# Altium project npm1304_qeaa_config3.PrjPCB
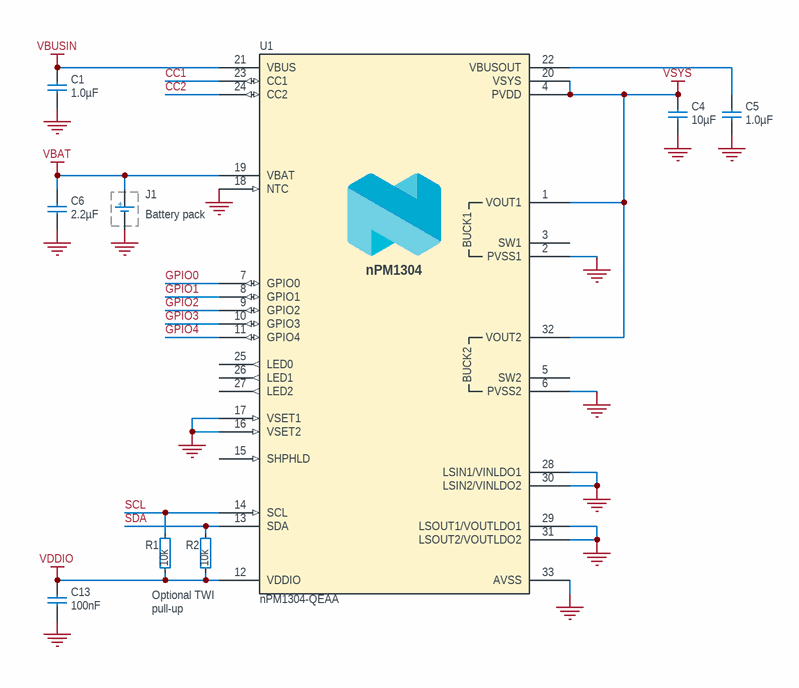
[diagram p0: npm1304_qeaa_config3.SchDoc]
1 sheet, 9 parts. Net scope: global (net labels, ports and power ports of the same name join across sheets).
Board file: npm1304_qeaa_config3.PcbDoc

## Sheet npm1304_qeaa_config3.SchDoc: nPM1304-QEAA Ref. Layout Config. 3
size A4; Revision: 1.0; SheetNumber: 1; SheetTotal: 1; DrawnBy: EISK; DocumentSize: A4; BoardTitle: nPM1304-QEAA Ref. Layout Config. 3; RefLayoutTitle: Minimal – only battery charging and VSYS output; Device: nPM1304-QEAA; Classification: PUBLIC; Config: 3

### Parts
C1  1.0µF  [CAPC1608X06L]
C4  10µF  [CAPC1608X06L]
C5  1.0µF  [CAPC1608X06L]
C6  2.2µF  [CAPC1608X06L]
C13  100nF  [CAPC0603X03L_C]
J1  Battery pack  [TP_2x1mm_TH]  (graphical)
R1  10k  [RESC0603X03L_C]
R2  10k  [RESC0603X03L_C]
U1  nPM1304-QEAA  [Nordic_QFN50P500X500X90-33N]

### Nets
GND: C1.1 C4.1 C5.1 C6.1 C13.2 J1.1(GND) U1.2(PVSS1) U1.6(PVSS2) U1.16(VSET2) U1.17(VSET1) U1.18(NTC) U1.28(LSIN1/VINLDO1) U1.29(LSOUT1/VOUTLDO1) U1.30(LSIN2/VINLDO2) U1.31(LSOUT2/VOUTLDO2) U1.33(AVSS)
VBAT: C6.2 J1.2(V+) U1.19(VBAT)
VBUSIN: C1.2 U1.21(VBUS)
VDDIO: C13.1 R1.2 R2.2 U1.12(VDDIO)
VSYS: C4.2 U1.1(VOUT1) U1.4(PVDD) U1.20(VSYS) U1.32(VOUT2)
CC1: U1.23(CC1)
CC2: U1.24(CC2)
GPIO0: U1.7(GPIO0)
GPIO1: U1.8(GPIO1)
GPIO2: U1.9(GPIO2)
GPIO3: U1.10(GPIO3)
GPIO4: U1.11(GPIO4)
SCL: R1.1 U1.14(SCL)
SDA: R2.1 U1.13(SDA)
NetC5_2: C5.2 U1.22(VBUSOUT)

Not connected (* = marked no-connect by the designer): U1 3(SW1) 5(SW2) 15(SHPHLD) 25(LED0) 26(LED1) 27(LED2)

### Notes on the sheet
- Optional TWI pull-up resistors

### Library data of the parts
C1 = C0603-1µ0-25V-X5R: Capacitor, X5R, ±10%, 25V; Manufacturer: N.A.; Part number NEMS: 100200687; Pad Count: 2; Component Status: Active
C4 = C0603-10µ: Capacitor, X5R, ±20%; Manufacturer: N.A.; Part number IPS: 00000007785; Part number NEMS: 100200275; Note: 6.3V; Artikkelnr Noca: 20039234; Pad Count: 2; Component Status: Active
C5 = C0603-1µ0-10V-X5R: Capacitor, Ceramic, 1.0µF 10V X5R 0603,±10%; Manufacturer: N.A.; Part number NEMS: 100200528; Pad Count: 2; Component Status: Active
C6 = C0603-2.2µ-16V-X7R: Capacitor, Ceramic, X7R, ±10%, 16V; Manufacturer: Taiyo Yuden; Manufacturer Part Number: EMK107BB7225KA-T; Part number NEMS: 100200439; Component Status: Active; Pad Count: 2; Artikkelnr Noca: N.A.
C13 = C0201-100n: Capacitor, X5R, ±10%, 100nF, 16V; Manufacturer: N.A.; Part number IPS: 00000001248, 00000002505; Part number Norautron: 262071862; Part number NEMS: 100200078; Pad Count: 2; Component Status: Active
J1 = Battery_TP: Manufacturer: N.A.; Part number NEMS: 101800006; Component Status: Active; Pad Count: 3
R1 R2 = R0201-10k: Resistor, ±1%, 0.05W; Manufacturer: N.A.; Part number IPS: 00000001255; Part number Norautron: 26107101; Part number NEMS: 100100065; Pad Count: 2; Note: Chip Res 1%; Component Status: Active
U1 = nPM1304-QEAA: Li-Ion/Li-Polymer USB-C battery charger with high efficiency buck regulators, LDOs or load switches, LED drivers, TWI and VBUSOUT; Manufacturer: Nordic Semiconductor; Part number NEMS: 102000396; Component Status: Active; Pad Count: 33; Artikkelnr Noca: N.A.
